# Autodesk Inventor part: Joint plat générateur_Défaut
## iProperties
Shininess: 64.0
Length Units: 11269
Angle Units: 11279
Time Units: 11290
Mass Units: 11283
Length Display Precision: 3
Angle Display Precision: 2
Compacted: True
Part Number: Joint plat générateur_Défaut
Document SubType Name: Modeling
Created: 2006-01
Material: Par défaut
Designer: riri
Density: 0.0
Volumn: 0.0
Area: 0.0
PropertySet Name: Model Information
Control State: 0
Master: False
Checked Out: False
Author: riri
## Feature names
1. Base1
